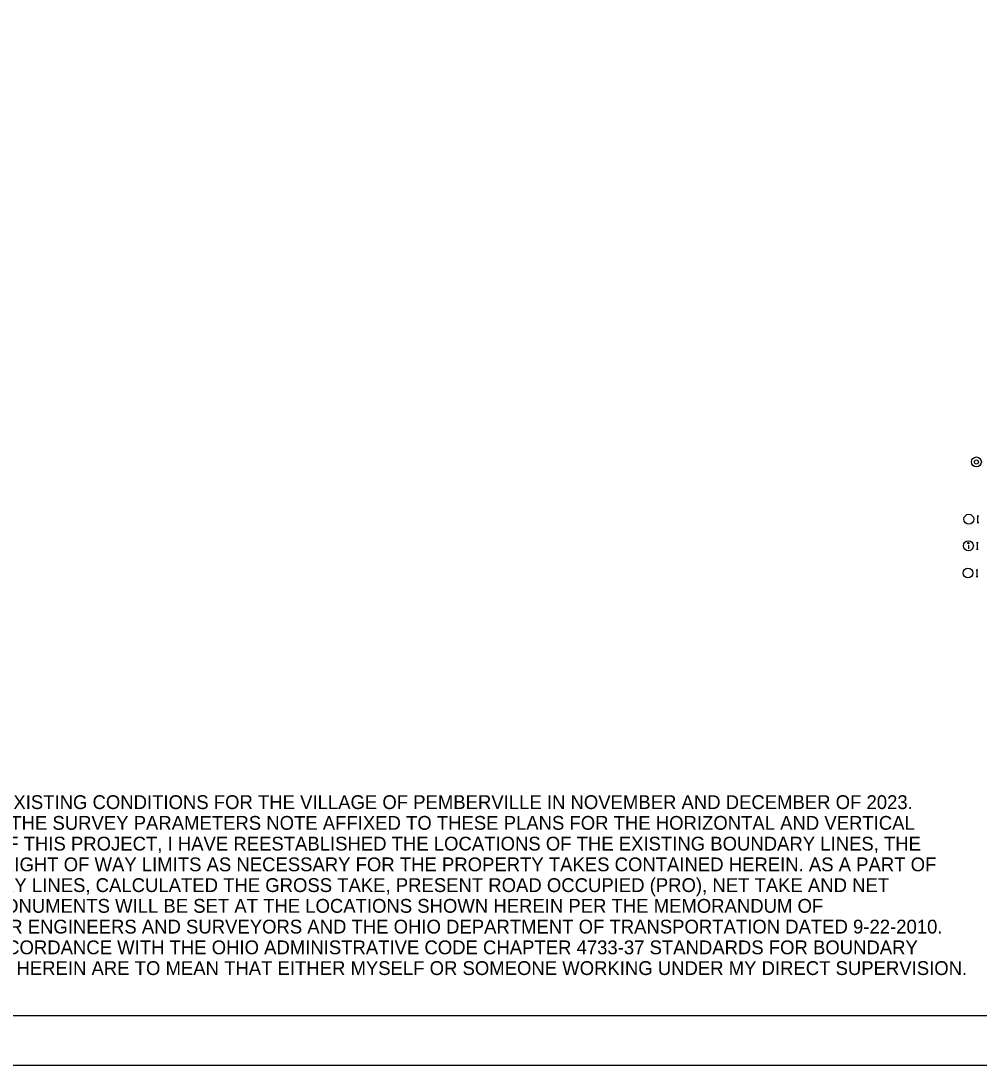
# Model space of a CAD drawing. Extents: x -4.7 to 34, y -3.1 to 22.
# Drawn here: x 14.65 to 24.35, y 0 to 10.57 of the extents above; entities that cross this region are included whole.
import ezdxf

# ---------------------------------------------------------------- set-up
doc = ezdxf.new("R2010")
doc.units = 0
for name, color, linetype in [('SC_Scratch2', 7, 'Continuous'), ('SH_Border', 7, 'Continuous'), ('SH_Cut_Line', 7, 'Continuous')]:
    doc.layers.add(name, color=color, linetype=linetype)

msp = doc.modelspace()

# ---------------------------------------------------------------- linework, layer by layer
at = {"layer": 'SC_Scratch2'}
for p, q in [((24.327, 5.56), (24.344, 5.56)), ((24.327, 5.56), (24.344, 5.56)), ((24.336, 5.493), (24.336, 5.56)), ((24.327, 5.493), (24.344, 5.493)), ((24.323, 5.29), (24.34, 5.29)), ((24.323, 5.29), (24.34, 5.29)), ((24.331, 5.224), (24.331, 5.29)), ((24.24, 5.262), (24.24, 5.225)), ((24.323, 5.224), (24.34, 5.224)), ((24.319, 5.014), (24.335, 5.014)), ((24.319, 5.014), (24.335, 5.014)), ((24.327, 4.947), (24.327, 5.014)), ((24.319, 4.947), (24.335, 4.947))]:
    msp.add_line(p, q, dxfattribs=at)
for centre, radius in [((24.321, 6.106), 0.05), ((24.321, 6.105), 0.0206), ((24.244, 5.526), 0.05), ((24.24, 5.257), 0.05), ((24.24, 5.284), 0.00667), ((24.235, 4.981), 0.05)]:
    msp.add_circle(centre, radius, dxfattribs=at)
at = {"layer": 'SH_Border'}
msp.add_lwpolyline([(1.5, 21.5), (33.5, 21.5), (33.5, 0.5), (1.5, 0.5)], close=True, dxfattribs=at)
at = {"layer": 'SH_Cut_Line'}
msp.add_lwpolyline([(0, 0), (34, 0), (34, 22), (0, 22)], close=True, dxfattribs=at)

# ---------------------------------------------------------------- texts
at = {"layer": 'SC_Scratch2'}
for s, p in [('I, R.J. LUMBREZER, P.S. HAVE CONDUCTED A SURVEY OF THE EXISTING CONDITIONS FOR THE VILLAGE OF PEMBERVILLE IN NOVEMBER AND DECEMBER OF 2023.', (8.697, 2.592)), ('THE RESULTS OF THAT SURVEY ARE CONTAINED HEREIN. SEE THE SURVEY PARAMETERS NOTE AFFIXED TO THESE PLANS FOR THE HORIZONTAL AND VERTICAL', (8.697, 2.382)), ('SURVEY PARAMETERS USED FOR THIS PROJECT. AS A PART OF THIS PROJECT, I HAVE REESTABLISHED THE LOCATIONS OF THE EXISTING BOUNDARY LINES, THE', (8.697, 2.172)), ('EXISTING CENTER LINE OF RIGHT OF WAY AND THE EXISTING RIGHT OF WAY LIMITS AS NECESSARY FOR THE PROPERTY TAKES CONTAINED HEREIN. AS A PART OF', (8.697, 1.962)), ('THIS PROJECT I HAVE ESTABLISHED THE PROPOSED BOUNDARY LINES, CALCULATED THE GROSS TAKE, PRESENT ROAD OCCUPIED (PRO), NET TAKE AND NET', (8.697, 1.752)), ('RESIDUE HEREIN. AS A PART OF THIS WORK, RIGHT OF WAY MONUMENTS WILL BE SET AT THE LOCATIONS SHOWN HEREIN PER THE MEMORANDUM OF', (8.697, 1.542)), ('UNDERSTANDING BETWEEN THE BOARD OF REGISTRATION FOR ENGINEERS AND SURVEYORS AND THE OHIO DEPARTMENT OF TRANSPORTATION DATED 9-22-2010.', (8.697, 1.332)), ('ALL OF MY WORK CONTAINED HEREIN WAS CONDUCTED IN ACCORDANCE WITH THE OHIO ADMINISTRATIVE CODE CHAPTER 4733-37 STANDARDS FOR BOUNDARY', (8.697, 1.122)), ('SURVEYS UNLESS SO NOTED. THE WORDS “I AND MY” AS USED HEREIN ARE TO MEAN THAT EITHER MYSELF OR SOMEONE WORKING UNDER MY DIRECT SUPERVISION.', (8.697, 0.912))]:
    msp.add_text(s, height=0.14, dxfattribs=at).set_placement(p)

doc.saveas('drawing.dxf')
